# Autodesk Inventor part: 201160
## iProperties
Created: 2007-10
Part Number: 201160
Document SubType Name: Modeling
Designer: TH
Density: 7.85 g/cm^3
Mass: 40.6964 g
Surface Area: 38.5523 cm^2
Volume: 5.18426 cm^3
Material: Steel
Description: PIVOT PLATE
Component Category: Lower Component
Author: TH
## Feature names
1. Extrusion1
2. Hole1
3. Hole2
